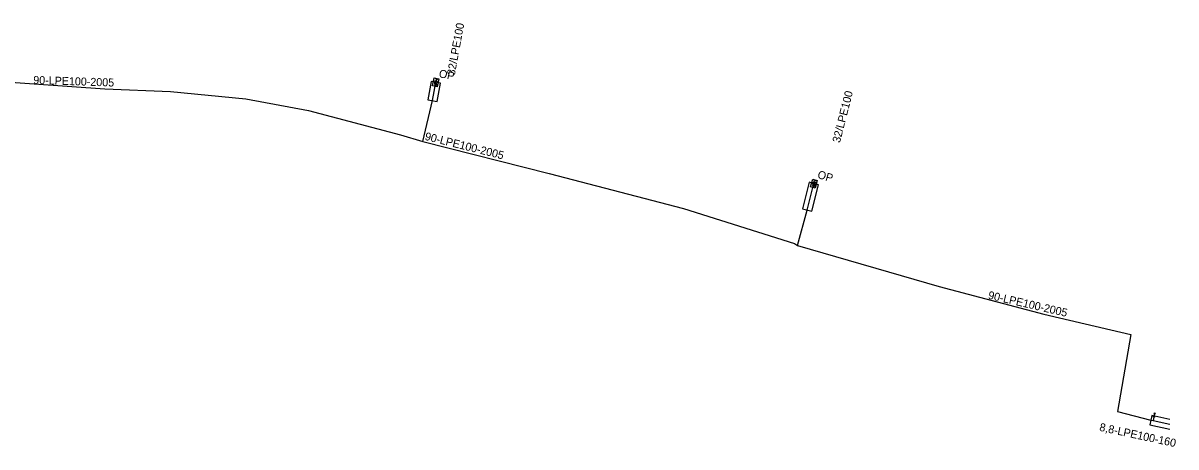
# Model space of a CAD drawing. Extents: x -762921 to -762499, y -1152946 to -1152170.
# Drawn here: x -762643.3 to -762499.2, y -1152946.1 to -1152893.2 of the extents above; entities that cross this region are included whole.
import ezdxf

# ---------------------------------------------------------------- set-up
doc = ezdxf.new("R2010")
doc.units = 0
for name, color, linetype in [('Vrstva 21', 7, 'Continuous'), ('Vrstva 28', 7, 'Continuous'), ('Vrstva 29', 7, 'Continuous'), ('Vrstva 31', 7, 'Continuous'), ('Vrstva 32', 7, 'Continuous')]:
    doc.layers.add(name, color=color, linetype=linetype)

msp = doc.modelspace()

# ---------------------------------------------------------------- linework, layer by layer
at = {"layer": 'Vrstva 21'}
for points in [[(-762646.67, -1152900.42), (-762633.1, -1152901.36), (-762624.89, -1152901.7), (-762615.47, -1152902.62), (-762607.65, -1152904.06), (-762596.16, -1152907.13), (-762593.37, -1152907.95), (-762577.56, -1152911.95), (-762560.79, -1152916.31), (-762546.89, -1152920.67), (-762546.55, -1152920.92), (-762528.82, -1152926.08), (-762515.73, -1152929.5), (-762507.39, -1152931.46)], [(-762507.39, -1152931.46), (-762504.85, -1152932.06), (-762506.52, -1152941.68), (-762502.37, -1152942.76), (-762502.08, -1152942.81), (-762500, -1152943.26)]]:
    msp.add_lwpolyline(points, dxfattribs=at)
at = {"layer": 'Vrstva 28'}
for p, q in [((-762501.989, -1152942.39), (-762502.08, -1152942.81)), ((-762501.96, -1152942.253), (-762501.869, -1152941.833))]:
    msp.add_line(p, q, dxfattribs=at)
msp.add_lwpolyline([(-762501.973, -1152941.984), (-762501.869, -1152941.833), (-762501.836, -1152942.014)], dxfattribs=at)
msp.add_circle((-762501.975, -1152942.322), 0.07, dxfattribs=at)
at = {"layer": 'Vrstva 29'}
for points in [[(-762592.33, -1152900.45), (-762592.75, -1152902.73), (-762591.57, -1152902.95), (-762591.15, -1152900.67)], [(-762545.06, -1152913.05), (-762545.91, -1152916.37), (-762544.75, -1152916.67), (-762543.9, -1152913.35)]]:
    msp.add_lwpolyline(points, close=True, dxfattribs=at)
msp.add_lwpolyline([(-762500, -1152942.66), (-762502.24, -1152942.17), (-762502.5, -1152943.35), (-762500, -1152943.89)], dxfattribs=at)
at = {"layer": 'Vrstva 31'}
for points in [[(-762593.37, -1152907.95), (-762592.16, -1152902.84), (-762591.74, -1152900.56)], [(-762546.55, -1152920.92), (-762545.33, -1152916.52), (-762544.48, -1152913.2)]]:
    msp.add_lwpolyline(points, dxfattribs=at)
at = {"layer": 'Vrstva 32'}
for p, q in [((-762591.953, -1152900.719), (-762591.61, -1152900.792)), ((-762591.87, -1152900.329), (-762591.527, -1152900.402)), ((-762591.485, -1152900.205), (-762591.828, -1152900.132)), ((-762591.647, -1152900.171), (-762591.689, -1152900.367)), ((-762544.201, -1152912.865), (-762544.538, -1152912.768)), ((-762544.36, -1152912.819), (-762544.416, -1152913.012)), ((-762544.704, -1152913.344), (-762544.368, -1152913.441)), ((-762544.593, -1152912.961), (-762544.257, -1152913.058))]:
    msp.add_line(p, q, dxfattribs=at)
for points in [[(-762591.342, -1152900.133), (-762591.551, -1152901.111), (-762592.138, -1152900.986), (-762591.929, -1152900.008), (-762591.342, -1152900.133)], [(-762591.548, -1152900.498), (-762591.793, -1152900.446), (-762591.844, -1152900.45), (-762591.883, -1152900.473), (-762591.908, -1152900.51), (-762591.914, -1152900.539), (-762591.907, -1152900.583), (-762591.88, -1152900.619), (-762591.835, -1152900.643), (-762591.59, -1152900.695)], [(-762591.61, -1152900.792), (-762591.638, -1152900.919), (-762591.663, -1152900.956), (-762591.682, -1152900.968), (-762591.717, -1152900.975), (-762591.766, -1152900.964), (-762591.795, -1152900.944), (-762591.808, -1152900.926), (-762591.816, -1152900.881), (-762591.788, -1152900.754)], [(-762544.053, -1152912.803), (-762544.331, -1152913.764), (-762544.907, -1152913.598), (-762544.63, -1152912.637), (-762544.053, -1152912.803)], [(-762544.284, -1152913.153), (-762544.526, -1152913.083), (-762544.577, -1152913.083), (-762544.617, -1152913.104), (-762544.645, -1152913.139), (-762544.653, -1152913.167), (-762544.648, -1152913.212), (-762544.625, -1152913.249), (-762544.581, -1152913.276), (-762544.34, -1152913.346)], [(-762544.368, -1152913.441), (-762544.404, -1152913.566), (-762544.432, -1152913.602), (-762544.451, -1152913.612), (-762544.487, -1152913.616), (-762544.535, -1152913.602), (-762544.563, -1152913.579), (-762544.574, -1152913.561), (-762544.579, -1152913.516), (-762544.543, -1152913.391)]]:
    msp.add_lwpolyline(points, dxfattribs=at)

# ---------------------------------------------------------------- texts
at = {"layer": 'Vrstva 21'}
for rotation, p in [(358.0636, (-762642.06, -1152900.75)), (345.87706, (-762593.18, -1152907.73)), (346.96379, (-762522.78, -1152927.58))]:
    msp.add_text('90-LPE100-2005', height=1, rotation=rotation, dxfattribs=at).set_placement(p)
at = {"layer": 'Vrstva 29'}
msp.add_text('8,8-LPE100-160', height=1, rotation=347.77382, dxfattribs=at).set_placement((-762508.86, -1152944.07))
at = {"layer": 'Vrstva 31'}
for rotation, p in [(79.56253, (-762589.37, -1152899.75)), (79.56253, (-762589.37, -1152899.75)), (75.63937, (-762541.23, -1152908.18)), (75.63937, (-762541.23, -1152908.18))]:
    msp.add_text('32/LPE100', height=1, rotation=rotation, dxfattribs=at).set_placement(p)
at = {"layer": 'Vrstva 32'}
for rotation, p in [(347.96484, (-762591.42, -1152899.9)), (347.96484, (-762591.42, -1152899.9)), (343.90061, (-762544.11, -1152912.5)), (343.90061, (-762544.11, -1152912.5))]:
    msp.add_text('OP', height=1, rotation=rotation, dxfattribs=at).set_placement(p)

doc.saveas('drawing.dxf')
